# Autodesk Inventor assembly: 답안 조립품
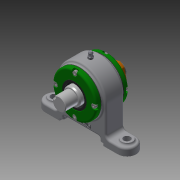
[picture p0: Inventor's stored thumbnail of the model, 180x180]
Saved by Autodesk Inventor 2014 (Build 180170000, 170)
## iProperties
Created: 2019-05
Part Number: 답안 조립품
Document SubType Name: Assembly
Designer: kh
Author: kh
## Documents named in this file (13)
- C:\Users\kh\Desktop\490504V1025\답안 조립품.iam
- C:\Users\kh\Desktop\490504V1025\본체.ipt
- C:\Users\kh\Desktop\490504V1025\개스킷.ipt
- C:\Users\kh\Desktop\490504V1025\그리스니플 M6.ipt
- 그리스니플  M6.ipt
- C:\Users\kh\Desktop\490504V1025\그리스니플개스킷.ipt
- C:\Users\kh\Desktop\490504V1025\베어링너트.ipt
- C:\Users\kh\Desktop\490504V1025\볼트 M4.ipt
- C:\Users\kh\Desktop\490504V1025\앵귤러 볼 베어링 7205.ipt
- C:\Users\kh\Desktop\490504V1025\오일 실 28 40 5 B.ipt
- C:\Users\kh\Desktop\490504V1025\축.ipt
- C:\Users\kh\Desktop\490504V1025\칼라.ipt
- C:\Users\kh\Desktop\490504V1025\커버.ipt
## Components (4 placed, 3 different names)
1. 개스킷:1 — Insert:9, Mate:4, Insert:10
2. 그리스니플  M6:1 — Insert:15
3. 그리스니플개스킷:1 — Insert:15, Insert:16
4. 개스킷:2 — Insert:8, Mate:3, Insert:11
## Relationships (8: Insert 6, Mate 2)
- Insert:8: 개스킷:2
- Mate:3: 개스킷:2
- Insert:9: 개스킷:1
- Mate:4: 개스킷:1
- Insert:10: 개스킷:1
- Insert:11: 개스킷:2
- Insert:15: 그리스니플  M6:1 ↔ 그리스니플개스킷:1
- Insert:16: 그리스니플개스킷:1
